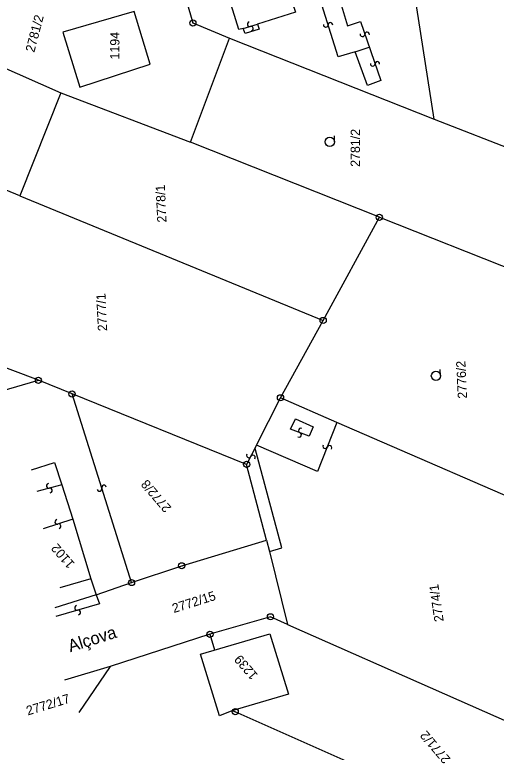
# Model space of a CAD drawing. Extents: x -658910 to -658078, y -1170373 to -1169331.
# Drawn here: x -658527.6 to -658449.7, y -1170123.2 to -1170003.8 of the extents above; entities that cross this region are included whole.
import ezdxf

# ---------------------------------------------------------------- set-up
doc = ezdxf.new("R2010")
doc.units = 0
doc.layers.add('Vrstva 8', color=7, linetype='Continuous')
doc.layers.add('Vrstva 9', color=7, linetype='Continuous')

msp = doc.modelspace()

# ---------------------------------------------------------------- linework, layer by layer
at = {"layer": 'Vrstva 8'}
for p, q in [((-658498.802, -1170005.199), (-658498.799, -1170005.1)), ((-658505.73, -1170011.82), (-658505.73, -1170011.82)), ((-658517.102, -1170015.539), (-658517.102, -1170015.539)), ((-658468.642, -1170036.67), (-658468.639, -1170036.571)), ((-658468.642, -1170036.67), (-658468.639, -1170036.571)), ((-658477.731, -1170053.369), (-658477.728, -1170053.27)), ((-658477.731, -1170053.369), (-658477.728, -1170053.27)), ((-658523.831, -1170063), (-658523.731, -1170063)), ((-658523.831, -1170063), (-658523.731, -1170063)), ((-658518.402, -1170065.211), (-658518.302, -1170065.211)), ((-658518.402, -1170065.211), (-658518.302, -1170065.211)), ((-658484.679, -1170065.83), (-658484.579, -1170065.83)), ((-658484.679, -1170065.83), (-658484.579, -1170065.83)), ((-658482.219, -1170069.26), (-658482.219, -1170069.26)), ((-658482.988, -1170070.891), (-658482.988, -1170070.891)), ((-658479.34, -1170070.539), (-658479.34, -1170070.539)), ((-658480, -1170072.07), (-658480, -1170072.07)), ((-658490.152, -1170076.609), (-658490.052, -1170076.609)), ((-658490.152, -1170076.609), (-658490.052, -1170076.609)), ((-658500.659, -1170093.031), (-658500.559, -1170093.031)), ((-658515.32, -1170095.121), (-658515.32, -1170095.121)), ((-658508.769, -1170095.75), (-658508.669, -1170095.75)), ((-658508.769, -1170095.75), (-658508.669, -1170095.75)), ((-658486.3, -1170101.289), (-658486.2, -1170101.289)), ((-658496.089, -1170104.121), (-658495.989, -1170104.121)), ((-658496.089, -1170104.121), (-658495.989, -1170104.121)), ((-658495.309, -1170106.629), (-658495.309, -1170106.629)), ((-658491.999, -1170116.66), (-658491.899, -1170116.66))]:
    msp.add_line(p, q, dxfattribs=at)
for points in [[(-658500.211, -1170000.27), (-658498.801, -1170005.15), (-658492.879, -1170007.641)], [(-658483.281, -1170000.219), (-658482.219, -1170003.41), (-658488.371, -1170005.359), (-658488.09, -1170006.15), (-658490.352, -1170006.84), (-658490.68, -1170006.059), (-658491.359, -1170006.24), (-658493.078, -1170000.621)], [(-658472.578, -1170009.809), (-658475.32, -1170010.641), (-658478.551, -1170000.289)], [(-658475.41, -1170000.15), (-658473.809, -1170005.609), (-658471.711, -1170004.941), (-658468.391, -1170014.49), (-658470.539, -1170015.289), (-658472.578, -1170009.809), (-658470.301, -1170009.059)], [(-658459.801, -1170020.74), (-658462.98, -1170000.219)], [(-658490.68, -1170006.059), (-658488.371, -1170005.359)], [(-658468.641, -1170036.621), (-658499.16, -1170024.449), (-658492.879, -1170007.641), (-658459.801, -1170020.74), (-658445.898, -1170026.1)], [(-658531.621, -1170008.283), (-658530.559, -1170011.891), (-658520.141, -1170016.441), (-658499.16, -1170024.449)], [(-658520.141, -1170016.441), (-658526.789, -1170033.129), (-658532.16, -1170030.949)], [(-658445.898, -1170026.1), (-658445.898, -1170026.1), (-658446.02, -1170045.57), (-658445.059, -1170046.301), (-658440.281, -1170048.02), (-658438.469, -1170085.941), (-658475.52, -1170069.85), (-658484.629, -1170065.83), (-658477.73, -1170053.32), (-658468.641, -1170036.621), (-658446.02, -1170045.57)], [(-658526.789, -1170033.129), (-658477.73, -1170053.32)], [(-658523.781, -1170063), (-658540.004, -1170056.895), (-658547.074, -1170034.758)], [(-658580.82, -1170062.693), (-658567.059, -1170058.518), (-658558.137, -1170061.963), (-658557.59, -1170064.049), (-658557.102, -1170065.688), (-658555.152, -1170072.094), (-658542.117, -1170068.344), (-658523.781, -1170063)], [(-658488.5, -1170073.48), (-658490.102, -1170076.609), (-658518.352, -1170065.211), (-658523.781, -1170063)], [(-658514.441, -1170097.73), (-658508.719, -1170095.75), (-658518.352, -1170065.211)], [(-658475.52, -1170069.85), (-658478.621, -1170077.781), (-658488.5, -1170073.48), (-658484.629, -1170065.83)], [(-658486.891, -1170088.859), (-658486.422, -1170090.73), (-658484.41, -1170090.1), (-658488.73, -1170074.07)], [(-658524.93, -1170077.48), (-658521.191, -1170076.33), (-658520.012, -1170079.9), (-658524.031, -1170081.01)], [(-658508.719, -1170095.75), (-658500.609, -1170093.031), (-658486.891, -1170088.859), (-658490.102, -1170076.609)], [(-658520.012, -1170079.9), (-658518.238, -1170085.5), (-658523.012, -1170087.031)], [(-658518.238, -1170085.5), (-658515.32, -1170095.121), (-658520.34, -1170096.59)], [(-658483.512, -1170102.52), (-658432.73, -1170124.961), (-658438.469, -1170085.941)], [(-658486.422, -1170090.73), (-658483.512, -1170102.52), (-658486.25, -1170101.289), (-658496.039, -1170104.121), (-658512.199, -1170109.32), (-658519.551, -1170111.551)], [(-658515.32, -1170095.121), (-658514.441, -1170097.73), (-658521.121, -1170099.85)], [(-658514.441, -1170097.73), (-658513.93, -1170099.199), (-658520.969, -1170101.25)], [(-658432.73, -1170124.961), (-658427.898, -1170145.15), (-658491.949, -1170116.66), (-658492.5, -1170116.51), (-658494.488, -1170117.301), (-658497.551, -1170107.359), (-658486.379, -1170104.051), (-658483.352, -1170113.789), (-658492.5, -1170116.51)], [(-658496.039, -1170104.121), (-658495.309, -1170106.629)], [(-658512.199, -1170109.32), (-658517.238, -1170116.76)]]:
    msp.add_lwpolyline(points, dxfattribs=at)
for points in [[(-658519.828, -1170006.65), (-658517.102, -1170015.539), (-658505.73, -1170011.82), (-658508.301, -1170003.301)], [(-658479.34, -1170070.539), (-658480, -1170072.07), (-658482.988, -1170070.891), (-658482.219, -1170069.26)]]:
    msp.add_lwpolyline(points, close=True, dxfattribs=at)
for centre in [(-658498.801, -1170005.15), (-658468.641, -1170036.621), (-658468.641, -1170036.621), (-658477.73, -1170053.32), (-658477.73, -1170053.32), (-658523.781, -1170063), (-658523.781, -1170063), (-658518.352, -1170065.211), (-658518.352, -1170065.211), (-658484.629, -1170065.83), (-658484.629, -1170065.83), (-658490.102, -1170076.609), (-658490.102, -1170076.609), (-658500.609, -1170093.031), (-658508.719, -1170095.75), (-658508.719, -1170095.75), (-658486.25, -1170101.289), (-658496.039, -1170104.121), (-658496.039, -1170104.121), (-658491.949, -1170116.66)]:
    msp.add_circle(centre, 0.499, dxfattribs=at)
for centre, radius, start, end in [((-658489.625, -1170005.349), 0.376, 100.02367, 286.33481), ((-658476.553, -1170005.469), 0.377, 351.08101, 178.74423), ((-658489.409, -1170006.071), 0.377, 279.34763, 107.01084), ((-658477.306, -1170005.448), 0.376, 171.75706, 358.06819), ((-658471.376, -1170006.987), 0.376, 171.75706, 358.06819), ((-658470.623, -1170007.008), 0.377, 351.08101, 178.74423), ((-658469.716, -1170011.768), 0.376, 171.75706, 358.06819), ((-658468.963, -1170011.789), 0.377, 351.08101, 178.74423), ((-658481.345, -1170071.131), 0.376, 61.4877, 247.79883), ((-658481.626, -1170071.83), 0.377, 240.81166, 68.47487), ((-658477.418, -1170073.667), 0.376, 151.66366, 337.97479), ((-658476.719, -1170073.946), 0.377, 330.98761, 158.65083), ((-658489.75, -1170075.156), 0.376, 144.58762, 330.89876), ((-658489.09, -1170075.519), 0.377, 323.91158, 151.5748), ((-658522.115, -1170080.096), 0.376, 98.37929, 284.69043), ((-658521.92, -1170080.824), 0.377, 277.70325, 105.36646), ((-658513.899, -1170080.589), 0.376, 190.53575, 16.84688), ((-658513.179, -1170080.366), 0.377, 9.85971, 197.52292), ((-658520.739, -1170085.91), 0.376, 100.7656, 287.07673), ((-658520.514, -1170086.628), 0.377, 280.08956, 107.75277), ((-658517.55, -1170099.856), 0.376, 99.27324, 285.58437), ((-658517.343, -1170100.58), 0.377, 278.59719, 106.26041)]:
    msp.add_arc(centre, radius, start, end, dxfattribs=at)
at = {"layer": 'Vrstva 9'}
for p, q in [((-658475.91, -1170024.403), (-658475.904, -1170023.404)), ((-658458.736, -1170062.241), (-658458.784, -1170061.243))]:
    msp.add_line(p, q, dxfattribs=at)
for centre in [(-658476.66, -1170024.399), (-658459.486, -1170062.277)]:
    msp.add_circle(centre, 0.75, dxfattribs=at)

# ---------------------------------------------------------------- texts
for s, height, rotation, p in [('2781/2', 1.5, 75.37005, (-658524.456, -1170010.01)), ('1194', 1.5, 89.7363, (-658510.692, -1170011.073)), ('2781/2', 1.5, 89.7363, (-658471.798, -1170028.446)), ('2778/1', 1.5, 92.73105, (-658503.054, -1170037.431)), ('2777/1', 1.5, 92.73105, (-658512.656, -1170055.017)), ('2776/2', 1.5, 92.73105, (-658454.444, -1170065.937)), ('2772/8', 1.5, 130.49568, (-658502.192, -1170083.602)), ('1102', 1.5, 130.49568, (-658517.818, -1170092.685)), ('2774/1', 1.5, 98.36046, (-658458.226, -1170101.985)), ('2772/15', 1.5, 17.50913, (-658501.879, -1170100.691)), ('Alçova', 2, 17.50913, (-658518.629, -1170107.039)), ('1239', 1.5, 130.49568, (-658488.199, -1170110.701)), ('2772/17', 1.5, 16.90871, (-658525.488, -1170117.27)), ('2771/2', 1.5, 130.49568, (-658457.05, -1170124.264))]:
    msp.add_text(s, height=height, rotation=rotation, dxfattribs=at).set_placement(p)

doc.saveas('drawing.dxf')
